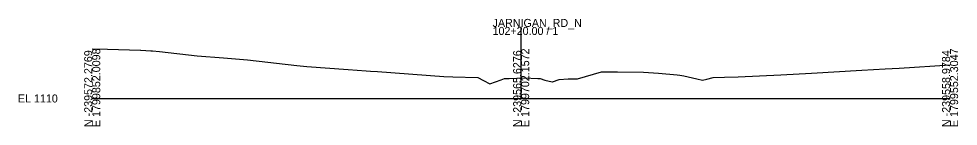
# Model space of a CAD drawing. Extents: x 214513 to 217151, y 214739 to 216780.
# Drawn here: x 216822.7 to 217151.2, y 215738.7 to 215776.2 of the extents above; entities that cross this region are included whole.
import ezdxf

# ---------------------------------------------------------------- set-up
doc = ezdxf.new("R2010")
doc.units = 0
for name, color, linetype in [('Section', 7, 'Continuous'), ('SURVEY - DTM GRAPHICS - Triangles', 7, 'Continuous'), ('XSCell', 7, 'Continuous')]:
    doc.layers.add(name, color=color, linetype=linetype)

msp = doc.modelspace()

# ---------------------------------------------------------------- linework, layer by layer
at = {"layer": 'SURVEY - DTM GRAPHICS - Triangles'}
msp.add_lwpolyline([(216848.36, 215765.76), (216853.73, 215765.61), (216865.18, 215765.19), (216865.36, 215765.19), (216868.85, 215765.01), (216869.43, 215764.98), (216871.84, 215764.76), (216885.07, 215763.32), (216894.22, 215762.58), (216902.69, 215761.84), (216919.93, 215759.9), (216923.41, 215759.5), (216937.84, 215758.48), (216944.16, 215758.02), (216945.65, 215757.89), (216948.13, 215757.76), (216971.36, 215755.99), (216974.47, 215755.95), (216983.23, 215755.7), (216985.2, 215754.59), (216987.36, 215753.49), (216991.35, 215754.92), (216992.58, 215755.35), (216994.12, 215755.4), (216999.37, 215755.55), (217004.2, 215755.34), (217005.03, 215755.29), (217006.69, 215754.81), (217009.15, 215754.12), (217009.36, 215754.2), (217011.63, 215755.05), (217014.76, 215755.2), (217017.99, 215755.26), (217018.01, 215755.26), (217018.06, 215755.27), (217026.48, 215757.62), (217027.1, 215757.66), (217028.37, 215757.71), (217032.04, 215757.67), (217041.16, 215757.57), (217046.43, 215757.15), (217052.86, 215756.65), (217053.85, 215756.49), (217055.22, 215756.31), (217059.8, 215755.25), (217061.79, 215754.78), (217063.24, 215755.15), (217065.5, 215755.68), (217069.45, 215755.77), (217074.22, 215755.87), (217089.2, 215756.64), (217099.94, 215757.26), (217117.49, 215758.2), (217125.65, 215758.69), (217130.52, 215758.97), (217148.36, 215760.09)], dxfattribs=at)
at = {"layer": 'XSCell'}
for p, q in [((216998.36, 215748.36), (216998.36, 215773.36)), ((216848.36, 215748.36), (216998.36, 215748.36)), ((216998.36, 215748.36), (217148.36, 215748.36))]:
    msp.add_line(p, q, dxfattribs=at)

# ---------------------------------------------------------------- texts
at = {"layer": 'Section'}
msp.add_text('-', height=0.0001, dxfattribs=at).set_placement((216848.36, 215748.36))
at = {"layer": 'XSCell'}
for s, p in [('JARNIGAN_RD_N', (216988.36, 215773.36)), ('102+20.00 / 1', (216988.36, 215770.56)), ('EL 1110', (216822.36, 215746.96))]:
    msp.add_text(s, height=2.8, dxfattribs=at).set_placement(p)
for s, p in [('N -239572.2769', (216848.36, 215738.36)), ('E 1799852.0098', (216851.16, 215738.36)), ('N -239565.6276', (216998.36, 215738.36)), ('E 1799702.1572', (217001.16, 215738.36)), ('N -239558.9784', (217148.36, 215738.36)), ('E 1799552.3047', (217151.16, 215738.36))]:
    msp.add_text(s, height=2.8, rotation=90, dxfattribs=at).set_placement(p)

doc.saveas('drawing.dxf')
